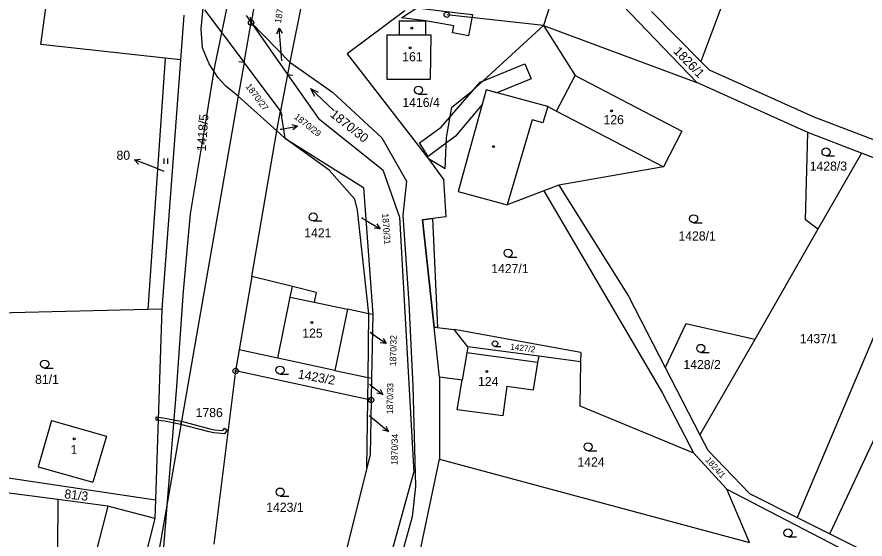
# Model space of a CAD drawing. Extents: x -546762 to -540209, y -1046851 to -1035694.
# Drawn here: x -543605.4 to -543447.5, y -1041018.4 to -1040921.1 of the extents above; entities that cross this region are included whole.
import ezdxf

# ---------------------------------------------------------------- set-up
doc = ezdxf.new("R2010")
doc.units = 0
for name, color, linetype in [('Vrstva 1', 7, 'Continuous'), ('Vrstva 16', 7, 'Continuous'), ('Vrstva 18', 7, 'Continuous'), ('Vrstva 19', 7, 'Continuous'), ('Vrstva 24', 7, 'Continuous'), ('Vrstva 25', 7, 'Continuous'), ('Vrstva 26', 7, 'Continuous'), ('Vrstva 3', 7, 'Continuous'), ('Vrstva 30', 7, 'Continuous'), ('Vrstva 37', 7, 'Continuous'), ('Vrstva 4', 7, 'Continuous'), ('Vrstva 52', 7, 'Continuous')]:
    doc.layers.add(name, color=color, linetype=linetype)

msp = doc.modelspace()

# ---------------------------------------------------------------- linework, layer by layer
at = {"layer": 'Vrstva 1'}
for p, q in [((-543571.06, -1040923.27), (-543569.82, -1040910.77)), ((-543552.01, -1040916.63), (-543554.53, -1040929.5)), ((-543562.71, -1040920.77), (-543561.76, -1040922.11)), ((-543561.76, -1040922.11), (-543554.53, -1040929.5)), ((-543570.79, -1040926.84), (-543571.06, -1040923.27)), ((-543569.57, -1040929.82), (-543570.79, -1040926.84)), ((-543567.9, -1040932.41), (-543569.57, -1040929.82)), ((-543563.06, -1040929.55), (-543564.16, -1040935.84)), ((-543554.53, -1040929.5), (-543554.98, -1040931.77)), ((-543554.53, -1040929.5), (-543546.63, -1040935.07)), ((-543566.47, -1040933.98), (-543567.9, -1040932.41)), ((-543564.16, -1040935.84), (-543566.47, -1040933.98)), ((-543546.63, -1040935.07), (-543537.4, -1040943.57)), ((-543564.16, -1040935.84), (-543585.58, -1041058.49)), ((-543556.95, -1040942.29), (-543564.16, -1040935.84)), ((-543556.95, -1040942.29), (-543556.31, -1040938.55)), ((-543561.61, -1040969.42), (-543556.95, -1040942.29)), ((-543555.46, -1040943.63), (-543556.95, -1040942.29)), ((-543547.21, -1040949.64), (-543555.46, -1040943.63)), ((-543537.4, -1040943.57), (-543532.84, -1040951.65)), ((-543542.43, -1040955), (-543547.21, -1040949.64)), ((-543532.84, -1040951.65), (-543533.51, -1040958.1)), ((-543541.98, -1040957.07), (-543542.43, -1040955)), ((-543539.85, -1040976.38), (-543541.98, -1040957.07)), ((-543533.51, -1040958.1), (-543532.43, -1040974.34)), ((-543532.43, -1040974.34), (-543531.66, -1040989.86)), ((-543539.85, -1040976.38), (-543543.79, -1040975.56)), ((-543540, -1040988.27), (-543539.85, -1040976.38)), ((-543539.13, -1040976.53), (-543539.85, -1040976.38)), ((-543540.05, -1040992.34), (-543564.64, -1040987.05)), ((-543546.17, -1040986.94), (-543540, -1040988.27)), ((-543540.05, -1040992.34), (-543540, -1040988.27)), ((-543540, -1040988.27), (-543539.35, -1040988.41)), ((-543531.66, -1040989.86), (-543531.15, -1041008.57)), ((-543540.21, -1041005.09), (-543540.05, -1040992.34)), ((-543539.42, -1040992.48), (-543540.05, -1040992.34)), ((-543539.61, -1041002.66), (-543540.21, -1041005.09)), ((-543540.21, -1041005.09), (-543546.36, -1041029.86)), ((-543531.15, -1041008.57), (-543531.75, -1041014.27)), ((-543531.75, -1041014.27), (-543537.3, -1041033.62))]:
    msp.add_line(p, q, dxfattribs=at)
for points in [[(-543454.19, -1040865.7), (-543478.04, -1040929.37)], [(-543558.98, -1040906.16), (-543561.76, -1040922.11)], [(-543600.9, -1040926.21), (-543598.38, -1040907.55)], [(-543503.35, -1040910.2), (-543507.35, -1040922.66)], [(-543494.17, -1040917.18), (-543478.76, -1040933.29)], [(-543574.29, -1040920.72), (-543574.92, -1040929.06)], [(-543570.42, -1040919.74), (-543563.06, -1040929.55)], [(-543533.12, -1040919.92), (-543543.91, -1040927.92)], [(-543507.35, -1040922.66), (-543525.34, -1040920.64)], [(-543487.23, -1040920.07), (-543478.04, -1040929.37)], [(-543561.76, -1040922.11), (-543554.98, -1040931.77)], [(-543534.21, -1040921.77), (-543534.21, -1040924.37)], [(-543534.21, -1040921.77), (-543529.31, -1040921.77)], [(-543529.31, -1040921.77), (-543529.31, -1040924.37)], [(-543520.73, -1040934.93), (-543507.35, -1040922.66)], [(-543507.35, -1040922.66), (-543478.76, -1040933.29)], [(-543507.35, -1040922.66), (-543501.41, -1040931.96)], [(-543536.51, -1040924.37), (-543536.51, -1040932.67)], [(-543536.51, -1040924.37), (-543534.21, -1040924.37)], [(-543529.31, -1040924.37), (-543528.31, -1040924.37)], [(-543528.31, -1040924.37), (-543528.41, -1040932.67)], [(-543577.79, -1040928.75), (-543600.9, -1040926.21)], [(-543577.79, -1040928.75), (-543580.97, -1040975.6)], [(-543574.92, -1040929.06), (-543578.41, -1040975.54)], [(-543574.92, -1040929.06), (-543577.79, -1040928.75)], [(-543543.91, -1040927.92), (-543528.74, -1040947.52)], [(-543556.31, -1040938.55), (-543563.06, -1040929.55)], [(-543478.04, -1040929.37), (-543476.44, -1040930.98)], [(-543554.98, -1040931.77), (-543549.2, -1040940)], [(-543504.91, -1040938.65), (-543501.41, -1040931.96)], [(-543501.41, -1040931.96), (-543481.6, -1040942.34)], [(-543456.92, -1040939.75), (-543476.44, -1040930.98)], [(-543536.51, -1040932.67), (-543528.41, -1040932.67)], [(-543458.14, -1040942.58), (-543478.76, -1040933.29)], [(-543524.37, -1040937.86), (-543520.73, -1040934.93)], [(-543517.98, -1040934.67), (-543523.24, -1040953.6)], [(-543506.54, -1040937.75), (-543517.98, -1040934.67)], [(-543556.31, -1040938.55), (-543555.46, -1040943.63)], [(-543525.41, -1040943.54), (-543524.37, -1040937.86)], [(-543506.54, -1040937.75), (-543504.91, -1040938.65)], [(-543549.2, -1040940), (-543537.27, -1040949.53)], [(-543432.51, -1040949.06), (-543456.92, -1040939.75)], [(-543481.6, -1040942.34), (-543485, -1040949.02)], [(-543458.55, -1040958.87), (-543458.14, -1040942.58)], [(-543448.12, -1040946.45), (-543458.14, -1040942.58)], [(-543555.46, -1040943.63), (-543540.87, -1040952.85)], [(-543525.65, -1040949.4), (-543525.41, -1040943.54)], [(-543448.12, -1040946.45), (-543456.25, -1040960.65)], [(-543433.75, -1040951.99), (-543448.12, -1040946.45)], [(-543525.65, -1040949.4), (-543528.74, -1040947.52)], [(-543528.74, -1040947.52), (-543525.96, -1040951.36)], [(-543537.27, -1040949.53), (-543534.12, -1040958.37)], [(-543485, -1040949.02), (-543504.46, -1040952.39)], [(-543525.96, -1040951.36), (-543525.52, -1040958.32)], [(-543504.46, -1040952.39), (-543507.28, -1040953.46)], [(-543504.46, -1040952.39), (-543491.53, -1040973.08)], [(-543433.75, -1040951.99), (-543460.13, -1041014.34)], [(-543540.87, -1040952.85), (-543539.13, -1040976.53)], [(-543523.24, -1040953.6), (-543514.12, -1040956.06)], [(-543507.28, -1040953.46), (-543514.12, -1040956.06)], [(-543507.28, -1040953.46), (-543485.15, -1040991.18)], [(-543454.04, -1041017.4), (-543425, -1040955.37)], [(-543534.12, -1040958.37), (-543531.44, -1041005.97)], [(-543525.52, -1040958.32), (-543529.83, -1040958.9)], [(-543529.83, -1040958.9), (-543527.68, -1040978.9)], [(-543456.25, -1040960.65), (-543458.55, -1040958.87)], [(-543456.25, -1040960.65), (-543468, -1040981.18)], [(-543561.61, -1040969.42), (-543563.96, -1040983.11)], [(-543554.08, -1040971.32), (-543561.61, -1040969.42)], [(-543549.67, -1040972.44), (-543554.08, -1040971.32)], [(-543549.67, -1040972.44), (-543550.05, -1040974.25)], [(-543491.53, -1040973.08), (-543484.66, -1040986.42)], [(-543550.05, -1040974.25), (-543543.79, -1040975.56)], [(-543580.97, -1040975.6), (-543621.68, -1040976.59)], [(-543578.41, -1040975.54), (-543580.97, -1040975.6)], [(-543578.41, -1040975.54), (-543579.59, -1041011.06)], [(-543539.13, -1040976.53), (-543539.35, -1040988.41)], [(-543526.68, -1040988.19), (-543527.68, -1040978.9)], [(-543527.68, -1040978.9), (-543523.95, -1040979.32)], [(-543521.41, -1040982.54), (-543523.95, -1040979.32)], [(-543500.4, -1040983.59), (-543523.95, -1040979.32)], [(-543480.86, -1040978.26), (-543484.66, -1040986.42)], [(-543468, -1040981.18), (-543480.86, -1040978.26)], [(-543468, -1040981.18), (-543478.2, -1040998.98)], [(-543508.23, -1040984.32), (-543521.41, -1040982.54)], [(-543563.96, -1040983.11), (-543564.64, -1040987.05)], [(-543556.81, -1040984.65), (-543563.96, -1040983.11)], [(-543508.23, -1040984.32), (-543508.42, -1040985.47)], [(-543500.43, -1040985.38), (-543508.23, -1040984.32)], [(-543500.4, -1040983.59), (-543500.43, -1040985.38)], [(-543546.17, -1040986.94), (-543556.81, -1040984.65)], [(-543508.42, -1040985.47), (-543509.25, -1040990.55)], [(-543500.43, -1040985.38), (-543500.56, -1040993.57)], [(-543564.64, -1040987.05), (-543568.73, -1041019.34)], [(-543484.66, -1040986.42), (-543478.2, -1040998.98)], [(-543539.35, -1040988.41), (-543539.42, -1040992.48)], [(-543522.46, -1040988.76), (-543526.68, -1040988.19)], [(-543526.68, -1040988.19), (-543526.68, -1041003.47)], [(-543523.39, -1040994.27), (-543522.46, -1040988.76)], [(-543514.16, -1040989.89), (-543514.91, -1040995.42)], [(-543514.16, -1040989.89), (-543509.25, -1040990.55)], [(-543485.15, -1040991.18), (-543479.4, -1041002.3)], [(-543539.42, -1040992.48), (-543539.61, -1041002.66)], [(-543500.56, -1040993.57), (-543479.4, -1041002.3)], [(-543514.91, -1040995.42), (-543523.39, -1040994.27)], [(-543598.94, -1040996.29), (-543601.41, -1041004.94)], [(-543598.94, -1040996.29), (-543588.69, -1040999.22)], [(-543588.69, -1040999.22), (-543591.2, -1041007.8)], [(-543478.2, -1040998.98), (-543476.75, -1041001.8)], [(-543479.4, -1041002.3), (-543473.2, -1041009.11)], [(-543476.75, -1041001.8), (-543468.96, -1041009.9)], [(-543531.89, -1041028.33), (-543526.68, -1041003.47)], [(-543526.68, -1041003.47), (-543468.97, -1041019.03)], [(-543611.59, -1041006.29), (-543579.59, -1041011.06)], [(-543601.41, -1041004.94), (-543591.2, -1041007.8)], [(-543538.08, -1041030.04), (-543531.44, -1041005.97)], [(-543597.75, -1041011.03), (-543610.7, -1041009.33)], [(-543468.97, -1041019.03), (-543473.2, -1041009.11)], [(-543473.2, -1041009.11), (-543430.31, -1041031.4)], [(-543597.75, -1041011.03), (-543597.93, -1041038.69)], [(-543588.46, -1041012.25), (-543597.75, -1041011.03)], [(-543579.59, -1041011.06), (-543579.71, -1041014.54)], [(-543468.96, -1041009.9), (-543460.13, -1041014.34)], [(-543579.71, -1041014.54), (-543588.46, -1041012.25)], [(-543460.13, -1041014.34), (-543454.04, -1041017.4)], [(-543579.71, -1041014.54), (-543586.53, -1041041.43)], [(-543454.04, -1041017.4), (-543429.99, -1041029.48)]]:
    msp.add_lwpolyline(points, dxfattribs=at)
at = {"layer": 'Vrstva 16'}
for p, q in [((-543556.32, -1040926.14), (-543556.56, -1040923.15)), ((-543556.08, -1040941.97), (-543553.13, -1040941.43)), ((-543580.7, -1040948.78), (-543583.49, -1040947.69)), ((-543540.32, -1040959.01), (-543537.74, -1040960.54)), ((-543539.08, -1040980.21), (-543536.64, -1040981.96)), ((-543539.63, -1040989.62), (-543537.23, -1040991.42)), ((-543538.51, -1040996.43), (-543536.21, -1040998.36))]:
    msp.add_line(p, q, dxfattribs=at)
for points in [[(-543556.98, -1040924.19), (-543556.56, -1040923.15), (-543555.98, -1040924.11)], [(-543556.07, -1040929.22), (-543556.32, -1040926.14)], [(-543554.2, -1040941.12), (-543553.13, -1040941.43), (-543554.02, -1040942.1)], [(-543556.34, -1040942.01), (-543556.08, -1040941.97)], [(-543582.74, -1040948.52), (-543583.49, -1040947.69), (-543582.38, -1040947.59)], [(-543577.97, -1040949.85), (-543580.7, -1040948.78)], [(-543541.22, -1040958.48), (-543540.32, -1040959.01)], [(-543538.35, -1040959.6), (-543537.74, -1040960.54), (-543538.86, -1040960.46)], [(-543539.6, -1040979.84), (-543539.08, -1040980.21)], [(-543537.16, -1040980.97), (-543536.64, -1040981.96), (-543537.75, -1040981.78)], [(-543539.75, -1040989.53), (-543539.63, -1040989.62)], [(-543537.73, -1040990.42), (-543537.23, -1040991.42), (-543538.33, -1040991.22)], [(-543539.81, -1040995.34), (-543538.51, -1040996.43)], [(-543536.66, -1040997.33), (-543536.21, -1040998.36), (-543537.3, -1040998.1)]]:
    msp.add_lwpolyline(points, dxfattribs=at)
at = {"layer": 'Vrstva 24'}
for centre, radius in [((-543525.34, -1040920.64), 0.5), ((-543561.76, -1040922.11), 0.5), ((-543561.76, -1040922.11), 0.1), ((-543564.64, -1040987.05), 0.5), ((-543564.64, -1040987.05), 0.1), ((-543539.42, -1040992.48), 0.5), ((-543539.42, -1040992.48), 0.1)]:
    msp.add_circle(centre, radius, dxfattribs=at)
at = {"layer": 'Vrstva 25'}
for p, q in [((-543530.61, -1040935.45), (-543529.01, -1040935.45)), ((-543577.95, -1040948.47), (-543577.95, -1040947.46)), ((-543577.28, -1040948.47), (-543577.28, -1040947.46)), ((-543454.73, -1040946.96), (-543453.13, -1040946.96)), ((-543550.21, -1040959.09), (-543548.61, -1040959.09)), ((-543479.38, -1040959.44), (-543477.78, -1040959.44)), ((-543513.92, -1040965.83), (-543512.32, -1040965.83)), ((-543516.36, -1040982.46), (-543515.29, -1040982.46)), ((-543478.06, -1040983.59), (-543476.46, -1040983.59)), ((-543600.2, -1040986.53), (-543598.6, -1040986.53)), ((-543556.39, -1040987.65), (-543554.79, -1040987.65)), ((-543499.02, -1041001.93), (-543497.42, -1041001.93)), ((-543556.35, -1041010.37), (-543554.75, -1041010.37)), ((-543461.81, -1041017.99), (-543460.21, -1041017.99))]:
    msp.add_line(p, q, dxfattribs=at)
for points in [[(-543546.34, -1040938.53), (-543550.7, -1040934.41), (-543549.95, -1040935.81)], [(-543550.7, -1040934.41), (-543549.27, -1040935.08)]]:
    msp.add_lwpolyline(points, dxfattribs=at)
for centre, radius in [((-543531.84, -1040923.15), 0.175), ((-543532.14, -1040926.83), 0.175), ((-543530.61, -1040934.7), 0.75), ((-543494.65, -1040938.56), 0.175), ((-543516.64, -1040945.23), 0.175), ((-543454.73, -1040946.21), 0.75), ((-543550.21, -1040958.34), 0.75), ((-543479.38, -1040958.69), 0.75), ((-543513.92, -1040965.08), 0.75), ((-543550.45, -1040978), 0.175), ((-543516.36, -1040981.96), 0.503), ((-543478.06, -1040982.84), 0.75), ((-543600.2, -1040985.78), 0.75), ((-543556.39, -1040986.9), 0.75), ((-543517.85, -1040987.14), 0.175), ((-543594.7, -1040999.72), 0.175), ((-543499.02, -1041001.18), 0.75), ((-543556.35, -1041009.62), 0.75), ((-543461.81, -1041017.24), 0.75)]:
    msp.add_circle(centre, radius, dxfattribs=at)
at = {"layer": 'Vrstva 26'}
for p, q in [((-543561.76, -1040922.11), (-543561.9, -1040921.12)), ((-543563.06, -1040929.55), (-543564.05, -1040929.41)), ((-543554.98, -1040931.77), (-543554, -1040931.94)), ((-543556.31, -1040938.55), (-543556.04, -1040939.51))]:
    msp.add_line(p, q, dxfattribs=at)
at = {"layer": 'Vrstva 3'}
for points in [[(-543536.51, -1040924.37), (-543536.51, -1040932.67)], [(-543536.51, -1040924.37), (-543534.21, -1040924.37)], [(-543534.21, -1040924.37), (-543529.31, -1040924.37)], [(-543529.31, -1040924.37), (-543528.31, -1040924.37)], [(-543528.31, -1040924.37), (-543528.41, -1040932.67)], [(-543504.91, -1040938.65), (-543501.41, -1040931.96)], [(-543501.41, -1040931.96), (-543481.6, -1040942.34)], [(-543536.51, -1040932.67), (-543528.41, -1040932.67)], [(-543504.91, -1040938.65), (-543485, -1040949.02)], [(-543481.6, -1040942.34), (-543485, -1040949.02)], [(-543556.81, -1040984.65), (-543554.49, -1040973.32)], [(-543554.49, -1040973.32), (-543550.05, -1040974.25)], [(-543550.05, -1040974.25), (-543543.79, -1040975.56)], [(-543543.79, -1040975.56), (-543546.17, -1040986.94)], [(-543521.61, -1040983.68), (-543522.46, -1040988.76)], [(-543508.42, -1040985.47), (-543521.61, -1040983.68)], [(-543546.17, -1040986.94), (-543556.81, -1040984.65)], [(-543508.42, -1040985.47), (-543509.25, -1040990.55)], [(-543523.39, -1040994.27), (-543522.46, -1040988.76)], [(-543514.16, -1040989.89), (-543514.91, -1040995.42)], [(-543514.16, -1040989.89), (-543509.25, -1040990.55)], [(-543514.91, -1040995.42), (-543523.39, -1040994.27)], [(-543598.94, -1040996.29), (-543601.41, -1041004.94)], [(-543598.94, -1040996.29), (-543588.69, -1040999.22)], [(-543588.69, -1040999.22), (-543591.2, -1041007.8)], [(-543601.41, -1041004.94), (-543591.2, -1041007.8)], [(-543588.46, -1041012.25), (-543590.42, -1041019.97)], [(-543579.71, -1041014.54), (-543588.46, -1041012.25)], [(-543579.71, -1041014.54), (-543586.53, -1041041.43)]]:
    msp.add_lwpolyline(points, dxfattribs=at)
at = {"layer": 'Vrstva 30'}
for points in [[(-543533.74, -1040921.22), (-543530.94, -1040919.39), (-543527.86, -1040919.76), (-543523.35, -1040920.3), (-543520.56, -1040920.63), (-543521.32, -1040924.58), (-543523.89, -1040924.08), (-543524.27, -1040924.01), (-543524.01, -1040922.7), (-543529.31, -1040921.77), (-543533.74, -1040921.22)], [(-543530.39, -1040944.53), (-543526.39, -1040941.62), (-543519.14, -1040933.24), (-543510.79, -1040929.82), (-543509.65, -1040932.6), (-543516.01, -1040935.2), (-543517.98, -1040934.67), (-543518.74, -1040937.41), (-543523.74, -1040943.3), (-543526.12, -1040945.08), (-543528.79, -1040947.07), (-543530.39, -1040944.53)], [(-543527.09, -1040978.97), (-543527.68, -1040978.9), (-543529.83, -1040958.9), (-543528.01, -1040958.65), (-543527.09, -1040978.97)], [(-543579.45, -1040996.23), (-543579.44, -1040995.63), (-543579.08, -1040995.67), (-543579.1, -1040996.27), (-543579.45, -1040996.23)], [(-543577.76, -1040995.82), (-543575.91, -1040996.21), (-543574.73, -1040996.39), (-543574.84, -1040997.01), (-543576.06, -1040996.79), (-543577.86, -1040996.42), (-543579.1, -1040996.27), (-543579.08, -1040995.67), (-543577.76, -1040995.82)], [(-543569.46, -1040997.82), (-543568.59, -1040998.01), (-543567, -1040998.15), (-543566.73, -1040997.74), (-543566.23, -1040998.06), (-543566.7, -1040998.8), (-543568.69, -1040998.61), (-543569.6, -1040998.4), (-543574.84, -1040997.01), (-543574.73, -1040996.39), (-543569.46, -1040997.82)]]:
    msp.add_lwpolyline(points, dxfattribs=at)
at = {"layer": 'Vrstva 37'}
for centre in [(-543532.14, -1040926.83), (-543494.65, -1040938.56), (-543550.45, -1040978), (-543517.85, -1040987.14), (-543594.7, -1040999.72)]:
    msp.add_circle(centre, 0.175, dxfattribs=at)
at = {"layer": 'Vrstva 4'}
for points in [[(-543563.06, -1040929.55), (-543561.76, -1040922.11)], [(-543534.21, -1040924.37), (-543529.31, -1040924.37)], [(-543554.98, -1040931.77), (-543556.31, -1040938.55)], [(-543506.54, -1040937.75), (-543507.44, -1040940.82)], [(-543504.91, -1040938.65), (-543485, -1040949.02)], [(-543509.46, -1040940.23), (-543514.12, -1040956.06)], [(-543507.44, -1040940.82), (-543509.46, -1040940.23)], [(-543554.49, -1040973.32), (-543554.08, -1040971.32)], [(-543556.81, -1040984.65), (-543554.49, -1040973.32)], [(-543554.49, -1040973.32), (-543550.05, -1040974.25)], [(-543543.79, -1040975.56), (-543546.17, -1040986.94)], [(-543521.41, -1040982.54), (-543521.61, -1040983.68)], [(-543521.61, -1040983.68), (-543522.46, -1040988.76)], [(-543508.42, -1040985.47), (-543521.61, -1040983.68)], [(-543588.46, -1041012.25), (-543590.42, -1041019.97)]]:
    msp.add_lwpolyline(points, dxfattribs=at)
at = {"layer": 'Vrstva 52'}
msp.add_lwpolyline([(-543566.29, -1040919.24), (-543568.59, -1040930.27), (-543570.16, -1040939.84), (-543573.12, -1040957.74), (-543574.39, -1040972.16), (-543575.66, -1040989.97), (-543578.21, -1041021.36)], dxfattribs=at)

# ---------------------------------------------------------------- texts
at = {"layer": 'Vrstva 16'}
for s, rotation, p in [('1870/28', 80.113, (-543556.22, -1040922.3)), ('1870/29', 321.3812, (-543553.87, -1040939.88)), ('1870/31', 274.2026, (-543537.38, -1040957.73)), ('1870/32', 88.9391, (-543534.77, -1040986.17)), ('1870/33', 89.0147, (-543535.36, -1040995.11)), ('1870/34', 88.9307, (-543534.51, -1041004.58))]:
    msp.add_text(s, height=1.2, rotation=rotation, dxfattribs=at).set_placement(p)
msp.add_text('80', height=1.7, dxfattribs=at).set_placement((-543586.82, -1040947.69))
at = {"layer": 'Vrstva 18'}
for s, height, rotation, p in [('1826/1', 1.7, 313.8403, (-543483.24, -1040927.57)), ('1870/27', 1.2, 306.8699, (-543562.86, -1040934.04)), ('1870/30', 1.7, 321.3812, (-543547.2, -1040939.48)), ('1418/5', 1.7, 85.7059, (-543570.21, -1040946.16)), ('1427/2', 1.14, 353.2186, (-543513.57, -1040983.07)), ('1423/2', 1.7, 349.9015, (-543553.14, -1040988.43)), ('1824/1', 1.14, 311.78, (-543477.28, -1041003.7)), ('81/3', 1.7, 353.4106, (-543596.6, -1041010.77))]:
    msp.add_text(s, height=height, rotation=rotation, dxfattribs=at).set_placement(p)
for s, height, p in [('1870/28', 0.1, (-543556.07, -1040929.22)), ('1416/4', 1.7, (-543533.6, -1040937.85)), ('1870/29', 0.1, (-543556.34, -1040942.01)), ('1428/3', 1.7, (-543457.77, -1040949.72)), ('80', 0.1, (-543578.04, -1040949.85)), ('1870/31', 0.1, (-543541.22, -1040958.48)), ('1421', 1.7, (-543551.87, -1040962.16)), ('1428/1', 1.7, (-543482.21, -1040962.74)), ('1427/1', 1.7, (-543517.06, -1040968.82)), ('1870/32', 0.1, (-543539.6, -1040979.84)), ('1437/1', 1.7, (-543459.61, -1040981.88)), ('1428/2', 1.7, (-543481.28, -1040986.71)), ('81/1', 1.7, (-543601.98, -1040989.47)), ('1870/33', 0.1, (-543539.75, -1040989.53)), ('1786', 1.7, (-543572.09, -1040995.66)), ('1870/34', 0.1, (-543539.81, -1040995.34)), ('1424', 1.7, (-543501.01, -1041004.87)), ('1423/1', 1.7, (-543558.94, -1041013.31))]:
    msp.add_text(s, height=height, dxfattribs=at).set_placement(p)
at = {"layer": 'Vrstva 19'}
for s, p in [('161', (-543533.63, -1040929.33)), ('126', (-543496.16, -1040941.05)), ('125', (-543552.23, -1040980.85)), ('124', (-543519.52, -1040989.87)), ('1', (-543595.37, -1041002.56))]:
    msp.add_text(s, height=1.7, dxfattribs=at).set_placement(p)

doc.saveas('drawing.dxf')
